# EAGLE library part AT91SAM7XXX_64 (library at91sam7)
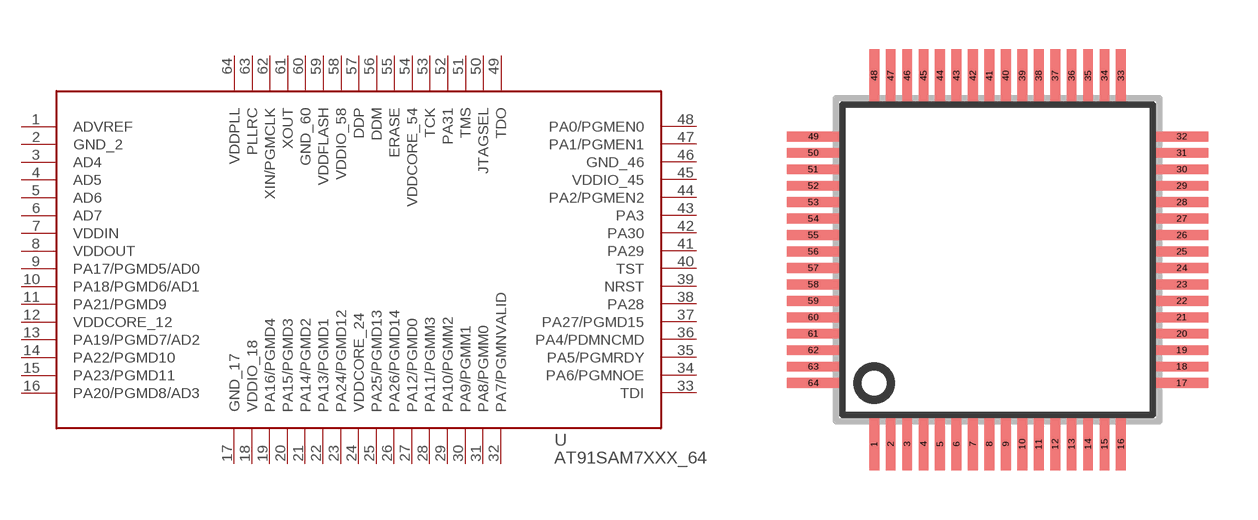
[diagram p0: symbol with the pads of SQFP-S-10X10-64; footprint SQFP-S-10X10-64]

Designator prefix U

## AT91SAM7XXX_64QFP64  [SQFP-S-10X10-64]
1  ADVREF
2  GND_2
3  AD4
4  AD5
5  AD6
6  AD7
7  VDDIN
8  VDDOUT
9  PA17/PGMD5/AD0
10  PA18/PGMD6/AD1
11  PA21/PGMD9
12  VDDCORE_12
13  PA19/PGMD7/AD2
14  PA22/PGMD10
15  PA23/PGMD11
16  PA20/PGMD8/AD3
17  GND_17
18  VDDIO_18
19  PA16/PGMD4
20  PA15/PGMD3
21  PA14/PGMD2
22  PA13/PGMD1
23  PA24/PGMD12
24  VDDCORE_24
25  PA25/PGMD13
26  PA26/PGMD14
27  PA12/PGMD0
28  PA11/PGMM3
29  PA10/PGMM2
30  PA9/PGMM1
31  PA8/PGMM0
32  PA7/PGMNVALID
33  TDI
34  PA6/PGMNOE
35  PA5/PGMRDY
36  PA4/PDMNCMD
37  PA27/PGMD15
38  PA28
39  NRST
40  TST
41  PA29
42  PA30
43  PA3
44  PA2/PGMEN2
45  VDDIO_45
46  GND_46
47  PA1/PGMEN1
48  PA0/PGMEN0
49  TDO
50  JTAGSEL
51  TMS
52  PA31
53  TCK
54  VDDCORE_54
55  ERASE
56  DDM
57  DDP
58  VDDIO_58
59  VDDFLASH
60  GND_60
61  XOUT
62  XIN/PGMCLK
63  PLLRC
64  VDDPLL

## Footprint SQFP-S-10X10-64 (pad centres in mm)
QFP64 shrink quad flat pack, square
smd 0.3 x 1.6: 1 -3.75,-5.6; 2 -3.25,-5.6; 3 -2.75,-5.6; 4 -2.25,-5.6; 5 -1.75,-5.6; 6 -1.25,-5.6; 7 -0.75,-5.6; 8 -0.25,-5.6; 9 0.25,-5.6; 10 0.75,-5.6; 11 1.25,-5.6; 12 1.75,-5.6; 13 2.25,-5.6; 14 2.75,-5.6; 15 3.25,-5.6; 16 3.75,-5.6; 33 3.75,5.6; 34 3.25,5.6; 35 2.75,5.6; 36 2.25,5.6; 37 1.75,5.6; 38 1.25,5.6; 39 0.75,5.6; 40 0.25,5.6; 41 -0.25,5.6; 42 -0.75,5.6; 43 -1.25,5.6; 44 -1.75,5.6; 45 -2.25,5.6; 46 -2.75,5.6; 47 -3.25,5.6; 48 -3.75,5.6
smd 1.6 x 0.3: 17 5.6,-3.75; 18 5.6,-3.25; 19 5.6,-2.75; 20 5.6,-2.25; 21 5.6,-1.75; 22 5.6,-1.25; 23 5.6,-0.75; 24 5.6,-0.25; 25 5.6,0.25; 26 5.6,0.75; 27 5.6,1.25; 28 5.6,1.75; 29 5.6,2.25; 30 5.6,2.75; 31 5.6,3.25; 32 5.6,3.75; 49 -5.6,3.75; 50 -5.6,3.25; 51 -5.6,2.75; 52 -5.6,2.25; 53 -5.6,1.75; 54 -5.6,1.25; 55 -5.6,0.75; 56 -5.6,0.25; 57 -5.6,-0.25; 58 -5.6,-0.75; 59 -5.6,-1.25; 60 -5.6,-1.75; 61 -5.6,-2.25; 62 -5.6,-2.75; 63 -5.6,-3.25; 64 -5.6,-3.75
